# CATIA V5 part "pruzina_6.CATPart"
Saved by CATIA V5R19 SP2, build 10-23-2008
Part number: Pruzina delka 17mm
Bounding box of the stored display mesh (mm): x -8 to 8, y -8 to 8, z 0 to 17
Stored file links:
  D:\DURATEC\pruzina_6.CATPart
  D:\DURATEC\pruzina_1.CATPart
  D:\DURATEC\Pohyb pruziny.CATProduct
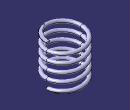
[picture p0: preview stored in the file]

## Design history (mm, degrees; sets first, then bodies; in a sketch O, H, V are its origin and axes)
External parameters (linked from other documents)
  `External.Delka pruziny` = 17 mm
  `External.Pocet zavitu` = 5
  `External.Vnitrni prumer pruziny` = 13 mm
  `External.Prumer dratu` = 1.5 mm
Set1
  Plane1: type Normal, Curve {line type PtDir, Direction (0, 0, 1), Start 0, End 17 {= `External.Delka pruziny`}, RefPoint {point type Coord, X 0, Y 0, Z 0}}, RefPoint vertex of Plane1
  Sketch1 on zx-plane, origin (0, 0, 0), H (-1, 0, 0), V (0, 0, 1)
    line L1 (6.5, 16) -> (6.5, 11)
    construction line L2 (6.5, 11) -> (-6.5, 11)
    line L3 (-6.5, 11) -> (-6.5, 16)
    construction line L4 (-6.5, 16) -> (6.5, 16)
    reference intersected line E1 through (0, 17) direction (-1, 0) from Plane1
    distance L3 L1 = 13 {= `External.Vnitrni prumer pruziny`}
    length L1 = 5
    distance L4 E1 = 1
    vertical: L1 V, L3 V
    horizontal: L2 H, L4 H
    equidistance: L1 L3 O
  Line1: type PtDir, Direction (0, 0, 1), Start 0, End 17 {= `External.Delka pruziny`}, RefPoint {point type Coord, X 0, Y 0, Z 0}
Body1 "Pruzina" (main body)
  Helix1: Pitch 3.4 {= `External.Delka pruziny` /`External.Pocet zavitu`}, TaperAngle 0, Height 17 {= Plane1.End}, Direction {line type PtDir, Direction (0, 0, 1), Start 0, End 17 {= `External.Delka pruziny`}, RefPoint {point type Coord, X 0, Y 0, Z 0}}, RefPoint {point type Coord, X 7.25 {= `External.Vnitrni prumer pruziny` /2+`External.Prumer dratu` /2}, Y 0, Z 0}
  Sketch2 on zx-plane, origin (0, 0, 0), H (-1, 0, 0), V (0, 0, 1)
    circle A1 centre (-7.25, 0) radius 0.75
    point P1 (-7.25, 0)
    reference projected point E1 (-7.25, 0) from vertex of Helix1
    radius A1 = 0.75 {= `External.Prumer dratu` /2}
    distance V A1 = 6.5 (reference)
    distance V A1 = 8 (reference)
    coincidence: P1 E1
  Rib1: profile Sketch2, centre curve Helix1
  Split1: SplitPlane xy-plane
  Split2: SplitPlane Plane1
